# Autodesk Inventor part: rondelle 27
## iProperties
Shininess: 20.0
Angle Display Precision: 2
Document Length Units: 11269
Document Angle Units: 11279
Document Time Units: 11290
Document Mass Units: 11283
Document Length Units Precision: 3
Document Angle Units Precision: 2
Compacted: True
Created: 2002-04
Part Number: rondelle 27
Material: Par défaut
Document SubType Name: Modélisation
Designer: thchene
Density: 0.0
Volumn: 0.0
Area: 0.0
PropertySet Name: Model Information
Control State: 0
Master: False
Checked Out: False
Author: thchene
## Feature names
1. Extrusion3
